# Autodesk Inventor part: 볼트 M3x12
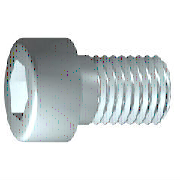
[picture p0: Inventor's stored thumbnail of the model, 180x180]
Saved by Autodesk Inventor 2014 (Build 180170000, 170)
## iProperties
IsCustomPart: 0
Created: 2012-02
Part Number: 볼트 M3x12
Material: 강철, 연강
Description: 6각머리 태핑 나사
Document SubType Name: Modeling
Standard: KS B 1003
Designer: mduedu
Standards Organization: KS
Language: ko-KR
Size Designation: M 3 x 12
Categories: <MemberInstance><Categories><Category DisplayName="조임쇠" InternalName="e4da775c-781d-43d5-af7c-5136215cf5a6" Mnemonic="FSTN"><Category DisplayName="볼트" InternalN
Density: 1 g/cm^3
Appearance: 강철
Author: mduedu
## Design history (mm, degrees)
sketch "스케치1"
  geometry: L1 (-0.867, 0)-(12, 0); L2 (12, 0)-(12, 1.5); L3 (12, 1.5)-(1.25, 1.5); L4 (1.25, 1.5)-(0.943, 1.5); L5 (0.943, 1.5)-(0, 1.5); L6 (0, 1.5)-(0, 2.75); L7 (0, 2.75)-(-3, 2.75); L8 (-3, 2.75)-(-3, 1.443); L9 (-3, 1.443)-(-1.7, 1.443); L10 (-1.7, 1.443)-(-0.867, 0); L11 (-6, 0)-(15, 0) reference; L12 (0, -0.55)-(0, 3.3) reference; L13 (1.25, 1.5)-(0, 1.5)
  constraints: 22 end point, 6 parallel, 2 collinear, 2 perpendicular, 1 horizontal, 1 point on line
  dimensions: "d1" = 10.75 distance from line of L3.end L2 (= GEL); "d2" = 0.30683 distance of L4.end L3.end (computed from GAL); "d3" = 3 distance between parallel lines of L8 L6 (= KOH); "d4" = 1.3 distance of L8.end L9.end (= INTI); "d5" = 60 deg angle of L10 L1; "d6" = 3 diameter of L3 L1 (= GD); "d7" = 3 diameter of L5 L1 (= BDM); "d8" = 2.88675 diameter of L9 L1 (= 1.1547 x SW); "d9" = 5.5 diameter of L7 L1 (= KOD); "d26" = 12 distance between parallel lines of L12 L2 (= NLG)
revolve "본체" sketch "스케치1" stored, may be unused: angle "d10" = 90 deg
sketch "스케치2"
  geometry: L1 (0, -3.85)-(0, 3.85) reference; L2 (-3.85, 0)-(3.85, 0) reference; L3 (1.443, 0)-(0.722, -1.25); L4 (0.722, -1.25)-(-0.722, -1.25); L5 (-0.722, -1.25)-(-1.443, 0); L6 (-1.443, 0)-(-0.722, 1.25); L7 (-0.722, 1.25)-(0.722, 1.25); L8 (0.722, 1.25)-(1.443, 0); 2 further points
  constraints: 12 end point, 1 coincident, 1 horizontal alignment, 1 point on line, 12 other
extrude "슬롯" join sketch "스케치2" stored distance "d11" = 10; taper "d12" = 0 deg
workplane "Work Plane1"
fillet "Fillet2" dims "d30" = 0.1 (= R)
body "Solid1"
fillet "모깎기1" dims "d17" = 0.3 (= RR)
feature "스레드" dims "d13" = 10.75 (= GEL), "d14" = 0
chamfer "모따기1" distance "d15" = 0.30673 (= -0.5 x SPD + 0.5 x GD); stored, may be unused: second distance "d16" = 0.30673 (= GUL), angle "d27" = 45 deg
other parameters: "GD" = 3 (= NND) [user parameter; used in 2 equation terms], "NLG" = 12 [user parameter; used in 1 equation term], "GEL" = 10.75 [user parameter; used in 2 equation terms], "KOD" = 5.5 [user parameter; used in 1 equation term], "KOH" = 3 [user parameter; used in 1 equation term], "INTI" = 1.3 [user parameter; used in 1 equation term], "GAL" = 0.30673 (= 0.61345 x PTC) [user parameter; used in 1 equation term], "GUL" = 0.30673 (= 0.61345 x PTC) [user parameter; used in 1 equation term], "BDM" = 3 (= NND) [user parameter; used in 1 equation term], "SW" = 2.5 [user parameter; used in 2 equation terms], "RR" = 0.3 [user parameter; used in 1 equation term], "SPD" = 2.38655 (= NND - 1.2269 x PTC) [user parameter; used in 1 equation term], "d19" = 0, "d28" = 0, "d29" = 0, "R" = 0.1 [user parameter; used in 1 equation term], "PHH" = 0.1 [user parameter], "GD1" = 2.38655 (= THREADDIA - 1.2269 x PTC) [user parameter], "THREADDIA" = 3 [user parameter; used in 1 equation term], "FAWI" = 45 deg [user parameter], "PTC" = 0.5 [user parameter; used in 5 equation terms], "NND" = 3 [user parameter; used in 3 equation terms], "TOA" = 30 deg [user parameter], "E0" = 2.8875 (= 1.155 x SW) [user parameter]
